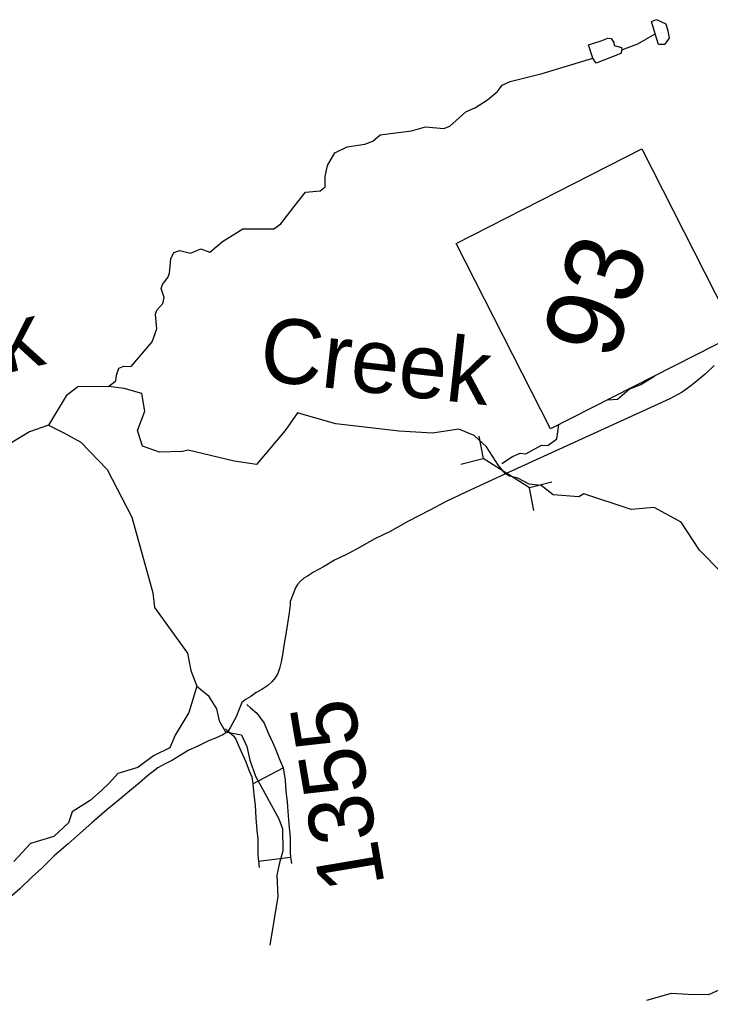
# Model space of a CAD drawing. Extents: x 1347947 to 1350662, y 1027710 to 1030532.
# Drawn here: x 1348247.6 to 1348295.7, y 1028932.1 to 1029000.4 of the extents above; entities that cross this region are included whole.
import ezdxf

# ---------------------------------------------------------------- set-up
doc = ezdxf.new("R2010")
doc.units = 0
doc.layers.add('Default', color=7, linetype='Continuous')
doc.layers.add('Prop Leader Line Light', color=7, linetype='Continuous')

msp = doc.modelspace()

# ---------------------------------------------------------------- linework, layer by layer
at = {"layer": 'Default'}
for p, q in [((1348279.557, 1028971.369), (1348279.865, 1028969.797)), ((1348278.312, 1028969.403), (1348279.865, 1028969.797)), ((1348283.09, 1028967.757), (1348279.865, 1028969.797)), ((1348284.643, 1028968.15), (1348283.09, 1028967.757)), ((1348283.399, 1028966.185), (1348283.09, 1028967.757)), ((1348263.84, 1028947.13), (1348265.94, 1028948.267)), ((1348264.23, 1028941.766), (1348266.464, 1028942.033))]:
    msp.add_line(p, q, dxfattribs=at)
for points in [[(1348291.842, 1028999.389), (1348291.587, 1029000.231), (1348291.943, 1029000.373), (1348292.596, 1029000.083), (1348292.728, 1028999.587), (1348292.818, 1028999.088), (1348292.501, 1028998.647), (1348292.086, 1028998.629), (1348291.842, 1028999.389)], [(1348289.513, 1028998.267), (1348290.639, 1028998.688), (1348291.842, 1028999.389)], [(1348287.513, 1028997.681), (1348287.21, 1028998.623), (1348288.079, 1028998.891), (1348288.557, 1028999.09), (1348288.788, 1028999.051), (1348288.96, 1028998.785), (1348288.987, 1028998.572), (1348289.49, 1028998.437), (1348289.513, 1028998.267)], [(1348289.513, 1028998.267), (1348289.442, 1028998.005), (1348287.739, 1028997.337), (1348287.513, 1028997.681)], [(1348253.793, 1028974.817), (1348254.298, 1028975.211), (1348254.334, 1028975.607), (1348254.506, 1028976.097), (1348254.861, 1028976.238), (1348255.36, 1028976.206), (1348256.822, 1028977.938), (1348257.159, 1028978.84), (1348257.046, 1028979.858), (1348257.141, 1028980.13), (1348257.568, 1028980.593), (1348257.655, 1028981.011), (1348257.451, 1028981.653), (1348257.546, 1028981.926), (1348257.918, 1028982.407), (1348258.026, 1028982.717), (1348258.127, 1028983.701), (1348258.322, 1028984.143), (1348258.744, 1028984.301), (1348259.49, 1028984.102), (1348260.207, 1028984.4), (1348260.843, 1028984.178), (1348261.712, 1028984.913), (1348262.756, 1028985.568), (1348263.144, 1028985.798), (1348265.305, 1028985.797), (1348265.772, 1028986.143), (1348266.703, 1028987.347), (1348267.504, 1028988.351), (1348268.516, 1028988.445), (1348268.861, 1028988.733), (1348268.866, 1028989.445), (1348269.029, 1028990.204), (1348269.548, 1028991.102), (1348270.406, 1028991.515), (1348271.632, 1028991.698), (1348272.177, 1028991.916), (1348272.696, 1028992.346), (1348274.873, 1028992.624), (1348275.845, 1028992.895), (1348277.133, 1028992.79), (1348277.556, 1028992.949), (1348278.66, 1028993.948), (1348279.341, 1028994.261), (1348280.159, 1028994.791), (1348280.867, 1028995.358), (1348281.191, 1028995.817), (1348281.749, 1028996.069), (1348283.979, 1028996.614), (1348287.513, 1028997.681)], [(1348295.945, 1028976.276), (1348295.317, 1028975.686), (1348294.43, 1028974.923), (1348293.734, 1028974.433), (1348292.873, 1028973.953), (1348281.43, 1028968.724), (1348278.673, 1028967.463), (1348277.298, 1028966.808), (1348276.157, 1028966.214), (1348274.612, 1028965.406), (1348273.386, 1028964.729), (1348272.316, 1028964.198), (1348271.049, 1028963.489), (1348270.359, 1028963.127), (1348269.526, 1028962.724), (1348268.762, 1028962.247), (1348268.064, 1028961.879), (1348267.646, 1028961.616), (1348267.389, 1028961.461), (1348267.155, 1028961.258), (1348266.951, 1028961.023), (1348266.807, 1028960.787), (1348266.681, 1028960.485), (1348266.427, 1028959.843), (1348266.421, 1028959.621), (1348266.365, 1028959.046), (1348266.251, 1028958.311), (1348266.164, 1028957.709), (1348266.014, 1028956.926), (1348265.9, 1028956.13), (1348265.815, 1028955.65), (1348265.693, 1028955.183), (1348265.567, 1028954.82), (1348265.38, 1028954.517), (1348265.188, 1028954.258), (1348264.874, 1028954.002), (1348264.469, 1028953.714), (1348264.069, 1028953.506), (1348263.689, 1028953.232), (1348263.368, 1028953.048), (1348263.063, 1028952.804), (1348262.837, 1028952.22), (1348262.667, 1028951.814)], [(1348288.558, 1028973.9), (1348289.214, 1028973.939), (1348290.028, 1028974.633), (1348290.854, 1028974.956), (1348291.817, 1028975.558)], [(1348281.43, 1028968.724), (1348280.931, 1028969.321), (1348280.112, 1028970.604), (1348279.247, 1028971.407), (1348278.178, 1028971.837), (1348276.335, 1028971.578), (1348274.015, 1028971.71), (1348269.61, 1028972.219), (1348267.742, 1028972.745), (1348266.952, 1028972.979), (1348266.074, 1028971.742), (1348264.079, 1028969.375), (1348262.532, 1028969.608), (1348259.326, 1028970.389), (1348258.93, 1028970.288), (1348257.336, 1028970.243), (1348256.157, 1028970.665), (1348255.798, 1028971.759), (1348256.309, 1028973.096), (1348256.108, 1028974.327), (1348254.88, 1028974.682), (1348253.793, 1028974.817), (1348251.637, 1028974.805), (1348250.829, 1028974.157), (1348249.598, 1028972.124)], [(1348249.598, 1028972.124), (1348248.29, 1028971.667), (1348246.972, 1028970.874), (1348246.323, 1028969.92), (1348243.678, 1028970.385), (1348242.731, 1028970.542), (1348240.855, 1028972.132), (1348240.167, 1028972.274), (1348238.829, 1028970.826), (1348236.238, 1028969.339), (1348234.617, 1028968.288), (1348232.66, 1028968.362), (1348231.713, 1028967.881), (1348228.752, 1028967.567), (1348226.309, 1028968.717), (1348226.063, 1028968.894), (1348226.047, 1028969.425), (1348227.945, 1028971.325), (1348227.934, 1028972.369)], [(1348249.598, 1028972.124), (1348250.665, 1028971.588), (1348251.846, 1028970.941), (1348253.684, 1028969.044), (1348255.403, 1028965.724), (1348256.877, 1028960.448), (1348256.981, 1028959.434), (1348259.287, 1028956.248), (1348259.518, 1028955.041), (1348259.926, 1028953.949)], [(1348281.179, 1028969.451), (1348281.904, 1028969.952), (1348282.448, 1028970.169), (1348282.844, 1028970.133), (1348283.93, 1028970.732), (1348284.375, 1028970.718), (1348285.002, 1028971.171), (1348285.141, 1028972.162)], [(1348314.729, 1028955.952), (1348310.551, 1028958.17), (1348308.62, 1028958.866), (1348307.394, 1028958.858), (1348306.346, 1028957.895), (1348304.931, 1028956.807), (1348303.655, 1028956.896), (1348301.678, 1028959.118), (1348298.102, 1028961.201), (1348296.458, 1028961.856), (1348294.926, 1028963.406), (1348293.647, 1028965.371), (1348291.776, 1028966.388), (1348290.182, 1028966.255), (1348286.877, 1028967.331), (1348286.539, 1028967.138), (1348284.746, 1028967.283), (1348283.907, 1028967.913), (1348283.063, 1028968.023), (1348282.292, 1028968.439), (1348281.705, 1028968.575), (1348281.43, 1028968.724)], [(1348259.926, 1028953.949), (1348259.381, 1028952.101), (1348258.426, 1028950.537), (1348258.054, 1028949.648), (1348256.913, 1028949.099), (1348255.824, 1028948.288), (1348254.429, 1028947.858), (1348253.853, 1028947.204), (1348253.304, 1028946.682), (1348252.508, 1028945.982), (1348251.254, 1028945.197), (1348250.987, 1028944.434), (1348249.974, 1028943.464), (1348248.353, 1028942.996), (1348247.185, 1028941.728)], [(1348259.926, 1028953.949), (1348260.719, 1028953.303), (1348261.309, 1028952.364), (1348261.485, 1028951.527), (1348261.93, 1028950.759), (1348263.043, 1028950.552), (1348263.406, 1028949.733), (1348263.629, 1028948.799), (1348264.014, 1028947.684), (1348265.644, 1028944.708), (1348265.907, 1028944.004), (1348265.92, 1028942.47), (1348265.657, 1028941.542), (1348265.493, 1028940.784), (1348265.562, 1028939.291), (1348265.005, 1028935.896)], [(1348263.412, 1028952.657), (1348263.665, 1028952.433), (1348264.114, 1028952.057), (1348264.623, 1028951.373), (1348264.883, 1028950.75), (1348265.206, 1028950.042), (1348265.431, 1028949.507), (1348265.659, 1028948.902), (1348265.94, 1028948.267), (1348266.077, 1028947.386), (1348266.134, 1028946.605), (1348266.226, 1028945.878), (1348266.291, 1028944.917), (1348266.359, 1028944.083), (1348266.422, 1028943.41), (1348266.429, 1028942.815), (1348266.427, 1028942.338), (1348266.464, 1028942.033), (1348266.518, 1028941.583)], [(1348262.667, 1028951.814), (1348262.438, 1028951.385), (1348262.276, 1028951.094), (1348262.114, 1028950.819), (1348261.791, 1028950.567), (1348261.232, 1028950.317), (1348260.754, 1028950.133), (1348260.055, 1028949.787), (1348259.334, 1028949.468), (1348258.844, 1028949.162), (1348258.235, 1028948.792), (1348257.719, 1028948.543), (1348257.229, 1028948.245), (1348256.792, 1028947.928), (1348256.492, 1028947.707), (1348255.925, 1028947.191), (1348255.266, 1028946.646), (1348254.546, 1028946.04), (1348253.666, 1028945.327), (1348252.62, 1028944.427), (1348251.801, 1028943.714), (1348250.969, 1028942.965), (1348250.003, 1028942.118), (1348249.132, 1028941.259), (1348248.449, 1028940.641), (1348247.617, 1028939.83), (1348247.062, 1028939.351)], [(1348261.922, 1028950.971), (1348262.198, 1028950.727), (1348262.467, 1028950.502), (1348262.653, 1028950.251), (1348262.821, 1028949.85), (1348263.145, 1028949.139), (1348263.341, 1028948.674), (1348263.576, 1028948.05), (1348263.762, 1028947.628), (1348263.84, 1028947.13), (1348263.895, 1028946.382), (1348263.985, 1028945.662), (1348264.047, 1028944.75), (1348264.117, 1028943.886), (1348264.173, 1028943.292), (1348264.178, 1028942.805), (1348264.177, 1028942.204), (1348264.23, 1028941.766), (1348264.283, 1028941.319)], [(1348306.104, 1028938.438), (1348306.136, 1028938.221), (1348305.936, 1028937.474), (1348304.713, 1028936.373), (1348303.111, 1028935.405), (1348301.699, 1028935.042), (1348300.278, 1028934.419), (1348299.701, 1028934.111), (1348299.368, 1028933.86), (1348298.46, 1028933.77), (1348295.548, 1028932.444), (1348294.131, 1028932.471), (1348292.969, 1028932.531), (1348291.233, 1028932.057)]]:
    msp.add_lwpolyline(points, dxfattribs=at)
msp.add_lwpolyline([(1348284.567, 1028971.87), (1348277.994, 1028984.789), (1348290.913, 1028991.362), (1348297.486, 1028978.443)], close=True, dxfattribs=at)

# ---------------------------------------------------------------- texts
for s, height, rotation, p in [('93', 5.3865, 71.96667, (1348288.976, 1028976.492)), ('Rock', 4.5, 13.2182, (1348236.165, 1028973.26)), ('Creek', 4.5, 353.74117, (1348264.174, 1028975.261))]:
    msp.add_text(s, height=height, rotation=rotation, dxfattribs=at).set_placement(p)
at = {"layer": 'Prop Leader Line Light'}
msp.add_text('1355', height=4.5, rotation=99.60014, dxfattribs=at).set_placement((1348273.027, 1028940.095))

doc.saveas('drawing.dxf')
